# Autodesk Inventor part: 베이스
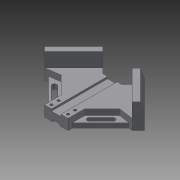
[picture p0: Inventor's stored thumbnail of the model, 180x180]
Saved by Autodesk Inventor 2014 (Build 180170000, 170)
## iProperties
Created: 2020-05
Part Number: 베이스
Material: Generic
Document SubType Name: Modeling
Designer: kh
Density: 1 g/cm^3
Appearance: Default
Author: kh
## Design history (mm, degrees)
sketch "Sketch1"
  geometry: L1 (0, 0)-(0, 298.702); L2 (-20, 0)-(20, 0); L3 (20, 0)-(84.853, 64.853); L4 (84.853, 64.853)-(35.355, 114.35); L5 (35.355, 114.35)-(16.005, 95); L6 (16.005, 95)-(-16.005, 95); L7 (-16.005, 95)-(-35.355, 114.35); L8 (-35.355, 114.35)-(-84.853, 64.853); L9 (-84.853, 64.853)-(-20, 0); 1 further point
  constraints: 18 end point, 4 perpendicular, 3 parallel, 2 midpoint, 1 point on line, 1 vertical
  dimensions: "d7" = 40 distance of L2.end L2.start; "d8" = 120 distance between parallel lines of L4 L9; "d10" = 50 distance between parallel lines of L4 L7; "d12" = 120 distance between parallel lines of L3 L8; "d13" = 50 distance from line of L4.end L8; "d14" = 95 distance between parallel lines of L2 L6
extrude "Extrusion1" new body sketch "Sketch1" distance "d15" = 18; taper "d16" = 0 deg
sketch "Sketch2"
  geometry: L1 (16.005, 95)-(-16.005, 95) reference; L2 (-20, 0)-(20, 0) reference; L3 (-8, 95)-(8, 95); L4 (8, 95)-(8, 0); L5 (8, 0)-(-8, 0); L6 (-8, 0)-(-8, 95); L7 (0, 0)-(0, 111.993)
  constraints: 10 end point, 3 parallel, 2 point on line, 1 horizontal, 1 perpendicular, 1 other
  dimensions: "d17" = 16 distance between parallel lines of L4 L6
extrude "Extrusion2" cut sketch "Sketch2" distance "d18" = 3.5; taper "d19" = 0 deg
sketch "Sketch3"
  geometry: L1 (-84.853, 64.853)-(-20, 0) reference; L2 (-35.355, 114.35)-(-84.853, 64.853) reference; L3 (-49.497, 57.782)-(-20, 28.284); L4 (-74.246, 54.246)-(-95.959, 32.534); L5 (-74.246, 54.246)-(-49.497, 57.782); L6 (-49.497, 57.782)-(-76.437, 30.842); L7 (-20, 0)-(-20, 28.284); L8 (-74.246, 54.246)-(-20, 0); 1 further point
  constraints: 12 end point, 2 perpendicular, 1 parallel, 1 point on line, 1 vertical
  dimensions: "d20" = 20 distance from line of L3.start L1; "d21" = 15 distance between parallel lines of L4 L2; "d22" = 30 distance between parallel lines of L6 L2
extrude "Extrusion3" cut sketch "Sketch3" distance "d23" = 10; taper "d24" = 0 deg
sketch "Sketch4"
  geometry: L1 (-20, 28.284)-(-20, 0) reference; L2 (-20, 0)-(-74.246, 54.246) reference; L3 (-68.059, 55.13)-(-20, 7.071); L4 (-20, 28.284)-(-20, 0) reference; L5 (-49.497, 57.782)-(-20, 28.284) reference; L6 (-74.246, 54.246)-(-49.497, 57.782) reference; L7 (-20, 0)-(-74.246, 54.246) reference; L8 (-74.246, 54.246)-(-20, 0); L9 (-20, 0)-(-20, 7.071); L10 (-74.246, 54.246)-(-68.059, 55.13); 1 further point
  constraints: 8 end point, 3 collinear, 2 point on line
  dimensions: "d25" = 5 distance between parallel lines of L3 L2
extrude "Extrusion4" cut sketch "Sketch4" distance "d26" = 10; taper "d27" = 0 deg
sketch "Sketch5"
  geometry: L1 (-68.059, 55.13)-(-20, 7.071) reference; L2 (-20, 28.284)-(-20, 7.071) reference; L3 (-49.497, 57.782)-(-20, 28.284) reference; L4 (-68.059, 55.13)-(-49.497, 57.782) reference; L5 (-49.497, 46.468)-(-29.698, 26.669); L6 (-52.326, 43.64)-(-32.527, 23.841); L7 (-26.87, 29.497)-(-46.669, 49.296); L8 (-35.355, 114.35)-(-84.853, 64.853) reference; A1 r 4 centre (-49.497, 46.468) between (-46.669, 49.296) and (-52.326, 43.64); A2 r 4 centre (-29.698, 26.669) between (-32.527, 23.841) and (-26.87, 29.497); 2 further points
  constraints: 8 end point, 4 point on circle, 4 tangent, 2 centre point, 2 parallel, 1 midpoint
  dimensions: "d28" = 8 distance between parallel lines of L7 L6; "d29" = 38 distance from line of L5.start L8; "d30" = 28 distance of L5.start L5.end; "d31" = 7 distance from line of L5.start L1
extrude "Extrusion5" cut sketch "Sketch5" stored distance "d32" = 10; taper "d33" = 0 deg
sketch "Sketch6"
  geometry: L1 (-84.853, 64.853)-(-74.246, 54.246) reference; L2 (-35.355, 114.35)-(-84.853, 64.853) reference; L3 (-16.005, 95)-(-35.355, 114.35) reference; L4 (-74.246, 54.246)-(-24.749, 103.744); L5 (-74.246, 54.246)-(-84.853, 64.853); L6 (-84.853, 64.853)-(-35.355, 114.35); L7 (-35.355, 114.35)-(-24.749, 103.744); 1 further point
  constraints: 8 end point, 2 collinear, 2 perpendicular, 1 point on line
extrude "Extrusion6" join sketch "Sketch6" distance "d34" = 24; taper "d35" = 0 deg
sketch "Sketch9"
  geometry: L1 (0, 0)-(-15, 0) reference; L2 (0, 42)-(0, 0) reference; L3 (-5, 0)-(0, 15); L4 (-5, 0)-(0.988, 0); L5 (0, 15)-(0, 0); 1 further point
  constraints: 6 end point, 2 perpendicular, 2 point on line
  dimensions: "d36" = 5 distance of L1.start L3.start; "d37" = 15 vertical distance of L3.end L3.start
extrude "Extrusion7" cut sketch "Sketch9" stored distance "d38" = 24; taper "d39" = 0 deg
mirror "Mirror1"
sketch "Sketch10"
  geometry: L1 (-16.005, 95)-(16.005, 95) reference; L2 (20, 0)-(-20, 0) reference; L3 (-6, 95)-(6, 95); L4 (6, 95)-(6, 0); L5 (6, 0)-(-6, 0); L6 (-6, 0)-(-6, 95); L7 (0, 0)-(0, 108.009)
  constraints: 10 end point, 3 parallel, 2 point on line, 1 horizontal, 1 perpendicular, 1 other
  dimensions: "d40" = 12 distance between parallel lines of L4 L6
extrude "Extrusion8" cut sketch "Sketch10" distance "d41" = 3; taper "d42" = 0 deg
sketch "Sketch11"
  geometry: L1 (0, 0)-(0, 51.762); L2 (20, 0)-(6, 0) reference; L3 (-20, 7.071)-(-20, 0) reference; L4 (20, 0)-(20, 7.071) reference; L5 (-74.246, 54.246)-(-84.853, 64.853) reference; L6 (84.853, 64.853)-(74.246, 54.246) reference; 4 further points
  constraints: 2 end point, 2 symmetric about line, 1 vertical
  dimensions: "d43" = 28 distance of point (14, 6) point (-14, 6); "d44" = 6 distance from line of point (14, 6) L2; "d45" = 12 distance of point (14, 18) point (14, 6); "d46" = 28 distance of point (14, 18) point (-14, 18)
hole "Hole1" sketch "Sketch11" at (-14, 6), (-14, 18), (14, 6), (14, 18) diameter "d47" = 4.5; stored, may be unused: countersink angle "d51" = 90 deg, drill point angle "d53" = 118 deg; dims "d48" = 6, "d49" = 8, "d50" = 10, "d52" = 8
body "Solid1"
node "Projected Loop1"
node "Projected Loop2"
